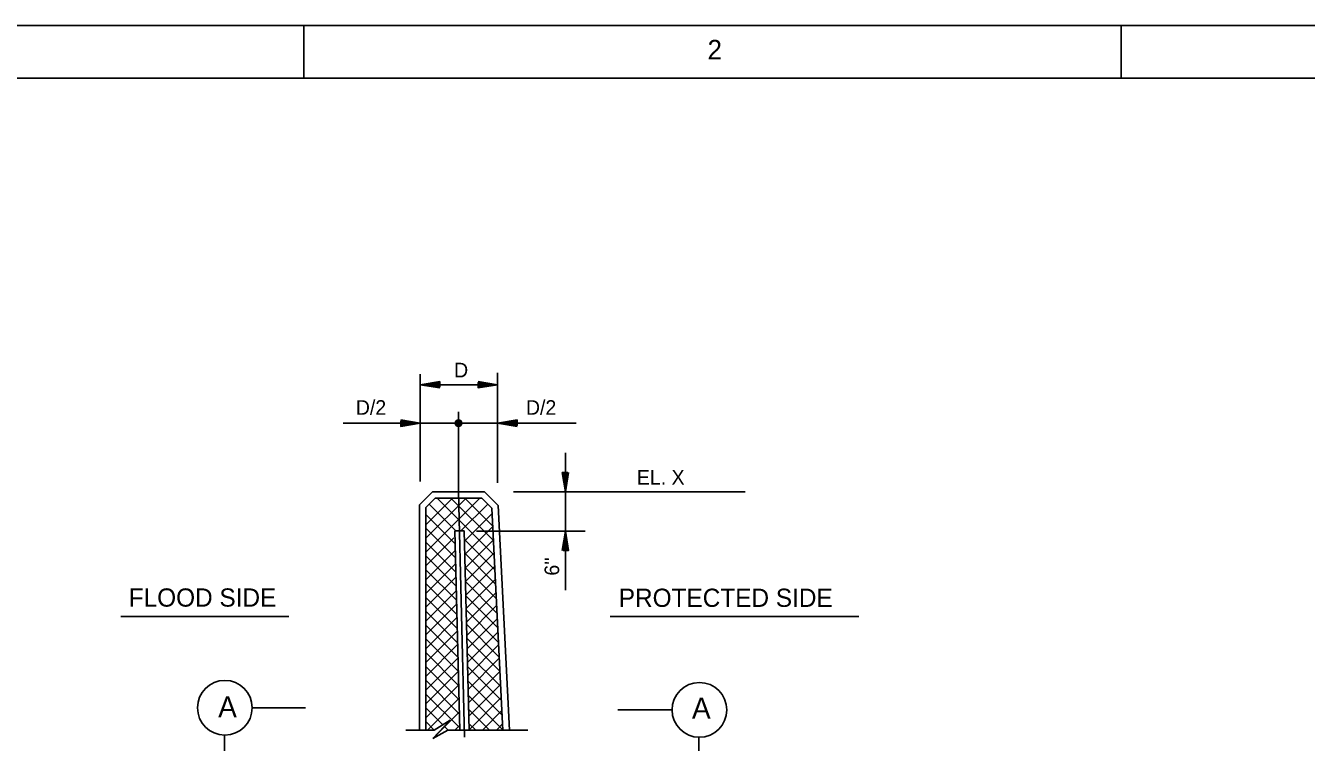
# Model space of a CAD drawing. Extents: x 44743.44 to 44747.1, y 44738.46 to 44741.29.
# Drawn here: x 44743.993 to 44745.018, y 44740.718 to 44741.292 of the extents above; entities that cross this region are included whole.
import ezdxf

# ---------------------------------------------------------------- set-up
doc = ezdxf.new("R2010")
doc.units = 0
for name, color, linetype in [('Level 1', 7, 'Continuous'), ('Level 10', 7, 'Continuous'), ('Level 2', 7, 'Continuous'), ('Level 3', 7, 'Continuous'), ('Level 8', 7, 'Continuous'), ('Level 9', 7, 'Continuous'), ('S-ANNO-TEXT', 7, 'Continuous')]:
    doc.layers.add(name, color=color, linetype=linetype)

msp = doc.modelspace()

# ---------------------------------------------------------------- linework, layer by layer
at = {"layer": 'Level 1'}
for p, q in [((44744.3088, 44740.927), (44744.3088, 44741.0131)), ((44744.3708, 44740.9261), (44744.3708, 44741.014)), ((44744.3088, 44741.0045), (44744.3708, 44741.0045)), ((44744.3088, 44741.0045), (44744.3088, 44741.0045)), ((44744.3131, 44741.0045), (44744.3131, 44741.0045)), ((44744.3664, 44741.0045), (44744.3664, 44741.0045)), ((44744.3708, 44741.0045), (44744.3708, 44741.0045)), ((44744.3394, 44740.9189), (44744.3394, 44740.9829)), ((44744.2472, 44740.9738), (44744.3088, 44740.9738)), ((44744.3044, 44740.9738), (44744.3044, 44740.9738)), ((44744.3088, 44740.9738), (44744.3708, 44740.9738)), ((44744.3088, 44740.9738), (44744.3088, 44740.9738)), ((44744.4336, 44740.9738), (44744.3708, 44740.9738)), ((44744.3708, 44740.9738), (44744.3708, 44740.9738)), ((44744.3751, 44740.9738), (44744.3751, 44740.9738)), ((44744.4251, 44740.9188), (44744.4251, 44740.95)), ((44744.3394, 44740.9189), (44744.3443, 44740.7225)), ((44744.3834, 44740.9188), (44744.5689, 44740.9188)), ((44744.4251, 44740.9231), (44744.4251, 44740.9231)), ((44744.4251, 44740.9188), (44744.4251, 44740.8875)), ((44744.4251, 44740.9188), (44744.4251, 44740.9188)), ((44744.3539, 44740.8875), (44744.4407, 44740.8875)), ((44744.4251, 44740.8402), (44744.4251, 44740.8875)), ((44744.4251, 44740.8875), (44744.4251, 44740.8875)), ((44744.4251, 44740.8832), (44744.4251, 44740.8832)), ((44744.32, 44740.7283), (44744.3133, 44740.735)), ((44744.3329, 44740.7361), (44744.319, 44740.7215)), ((44744.3199, 44740.7283), (44744.3329, 44740.7361)), ((44744.2974, 44740.7283), (44744.3199, 44740.7283)), ((44744.3091, 44740.7283), (44744.3082, 44740.7291)), ((44744.319, 44740.7215), (44744.3308, 44740.7283)), ((44744.3311, 44740.7283), (44744.3282, 44740.7312)), ((44744.3308, 44740.7283), (44744.395, 44740.7283))]:
    msp.add_line(p, q, dxfattribs=at)
msp.add_lwpolyline([(44743.438, 44741.2918), (44747.1047, 44741.2918), (44747.1047, 44738.4578), (44743.438, 44738.4578)], close=True, dxfattribs=at)
for points in [[(44744.3244, 44741.002), (44744.3088, 44741.0045), (44744.3244, 44741.0071), (44744.3244, 44741.0027), (44744.3131, 44741.0045), (44744.3237, 44741.0063), (44744.3237, 44741.0035), (44744.3173, 44741.0045), (44744.323, 44741.0055), (44744.323, 44741.0043), (44744.3216, 44741.0045)], [(44744.3552, 44741.0071), (44744.3708, 44741.0045), (44744.3552, 44741.002), (44744.3552, 44741.0064), (44744.3664, 44741.0045), (44744.3558, 44741.0028), (44744.3558, 44741.0056), (44744.3623, 44741.0045), (44744.3565, 44741.0036), (44744.3565, 44741.0048), (44744.3579, 44741.0045)], [(44744.2932, 44740.9764), (44744.3088, 44740.9738), (44744.2932, 44740.9712), (44744.2932, 44740.9756), (44744.3044, 44740.9738), (44744.2939, 44740.972), (44744.2939, 44740.9749), (44744.3003, 44740.9738), (44744.2945, 44740.9729), (44744.2945, 44740.974), (44744.2959, 44740.9738)], [(44744.3863, 44740.9712), (44744.3708, 44740.9738), (44744.3863, 44740.9764), (44744.3863, 44740.9719), (44744.3751, 44740.9738), (44744.3857, 44740.9755), (44744.3857, 44740.9727), (44744.3793, 44740.9738), (44744.385, 44740.9747), (44744.385, 44740.9735), (44744.3836, 44740.9738)], [(44744.4276, 44740.9343), (44744.4251, 44740.9188), (44744.4225, 44740.9343), (44744.4269, 44740.9343), (44744.4251, 44740.9231), (44744.4233, 44740.9337), (44744.4261, 44740.9337), (44744.4251, 44740.9273), (44744.4241, 44740.933), (44744.4253, 44740.933), (44744.4251, 44740.9316)], [(44744.4225, 44740.872), (44744.4251, 44740.8875), (44744.4276, 44740.872), (44744.4232, 44740.872), (44744.4251, 44740.8832), (44744.4268, 44740.8726), (44744.424, 44740.8726), (44744.4251, 44740.879), (44744.426, 44740.8733), (44744.4248, 44740.8733), (44744.4251, 44740.8747)]]:
    msp.add_lwpolyline(points, dxfattribs=at)
at = {"layer": 'Level 10'}
for p, q in [((44744.2157, 44741.2498), (44744.2157, 44741.2918)), ((44744.8697, 44741.2498), (44744.8697, 44741.2918)), ((44744.3186, 44740.9189), (44744.3082, 44740.9085)), ((44744.3186, 44740.9189), (44744.3602, 44740.9189)), ((44744.3602, 44740.9189), (44744.3712, 44740.908)), ((44744.3082, 44740.9085), (44744.3082, 44740.7283)), ((44744.3712, 44740.908), (44744.3802, 44740.7283)), ((44744.0693, 44740.8191), (44744.2036, 44740.8191)), ((44744.6597, 44740.8191), (44744.4608, 44740.8191))]:
    msp.add_line(p, q, dxfattribs=at)
at = {"layer": 'Level 2'}
for p, q in [((44744.3422, 44740.9738), (44744.337, 44740.9738)), ((44744.3418, 44740.9751), (44744.3373, 44740.9751)), ((44744.3418, 44740.9725), (44744.3373, 44740.9725)), ((44744.3389, 44740.9712), (44744.3397, 44740.9712)), ((44744.3207, 44740.9138), (44744.3133, 44740.9064)), ((44744.3207, 44740.9138), (44744.3581, 44740.9138)), ((44744.3581, 44740.9138), (44744.3661, 44740.9057)), ((44744.3133, 44740.9064), (44744.3133, 44740.7283)), ((44744.3661, 44740.9057), (44744.375, 44740.728)), ((44744.3365, 44740.8877), (44744.344, 44740.8877)), ((44744.3365, 44740.8877), (44744.3405, 44740.7283)), ((44744.344, 44740.8877), (44744.3479, 44740.7283))]:
    msp.add_line(p, q, dxfattribs=at)
msp.add_circle((44744.3395, 44740.9738), 0.00261, dxfattribs=at)
at = {"layer": 'Level 3'}
for p, q in [((44744.217, 44740.7461), (44744.1739, 44740.7461)), ((44744.4669, 44740.7444), (44744.5099, 44740.7444)), ((44744.1521, 44740.7097), (44744.1521, 44740.7243)), ((44744.5318, 44740.7079), (44744.5318, 44740.7225))]:
    msp.add_line(p, q, dxfattribs=at)
for centre in [(44744.1525, 44740.7461), (44744.5322, 44740.7444)]:
    msp.add_circle(centre, 0.0219, dxfattribs=at)
at = {"layer": 'Level 8'}
for p, q in [((44744.3133, 44740.8706), (44744.3565, 44740.9138)), ((44744.3133, 44740.8817), (44744.3455, 44740.9138)), ((44744.3133, 44740.8925), (44744.3346, 44740.9138)), ((44744.3161, 44740.9091), (44744.3374, 44740.8877)), ((44744.368, 44740.8682), (44744.3224, 44740.9138)), ((44744.3674, 44740.8798), (44744.3334, 44740.9138)), ((44744.3414, 44740.8877), (44744.3628, 44740.9091)), ((44744.3669, 44740.8914), (44744.3445, 44740.9138)), ((44744.3367, 44740.8773), (44744.3133, 44740.9007)), ((44744.3442, 44740.8794), (44744.3664, 44740.9016)), ((44744.337, 44740.866), (44744.3133, 44740.8897)), ((44744.3444, 44740.8686), (44744.3669, 44740.891)), ((44744.3133, 44740.8596), (44744.3358, 44740.882)), ((44744.3373, 44740.8547), (44744.3133, 44740.8786)), ((44744.3686, 44740.8565), (44744.3441, 44740.881)), ((44744.3447, 44740.8578), (44744.3674, 44740.8805)), ((44744.3133, 44740.8485), (44744.3368, 44740.872)), ((44744.3376, 44740.8434), (44744.3133, 44740.8676)), ((44744.3692, 44740.8449), (44744.3444, 44740.8697)), ((44744.345, 44740.847), (44744.3679, 44740.87)), ((44744.3133, 44740.8375), (44744.3371, 44740.8613)), ((44744.3698, 44740.8332), (44744.3447, 44740.8583)), ((44744.3452, 44740.8363), (44744.3685, 44740.8595)), ((44744.3378, 44740.8321), (44744.3133, 44740.8565)), ((44744.3133, 44740.8265), (44744.3374, 44740.8505)), ((44744.3704, 44740.8216), (44744.345, 44740.847)), ((44744.3455, 44740.8255), (44744.369, 44740.849)), ((44744.3381, 44740.8207), (44744.3133, 44740.8454)), ((44744.3133, 44740.8154), (44744.3377, 44740.8397)), ((44744.3458, 44740.8147), (44744.3695, 44740.8384)), ((44744.3384, 44740.8094), (44744.3133, 44740.8344)), ((44744.3133, 44740.8044), (44744.3379, 44740.8289)), ((44744.3709, 44740.81), (44744.3453, 44740.8357)), ((44744.3461, 44740.8039), (44744.37, 44740.8279)), ((44744.3387, 44740.798), (44744.3133, 44740.8233)), ((44744.3133, 44740.7933), (44744.3382, 44740.8182)), ((44744.3715, 44740.7984), (44744.3455, 44740.8244)), ((44744.3463, 44740.7932), (44744.3706, 44740.8174)), ((44744.339, 44740.7867), (44744.3133, 44740.8123)), ((44744.3133, 44740.7823), (44744.3385, 44740.8074)), ((44744.3721, 44740.7867), (44744.3458, 44740.813)), ((44744.3466, 44740.7824), (44744.3711, 44740.8069)), ((44744.3393, 44740.7753), (44744.3133, 44740.8012)), ((44744.3133, 44740.7712), (44744.3387, 44740.7966)), ((44744.3727, 44740.7751), (44744.3461, 44740.8017)), ((44744.3469, 44740.7716), (44744.3716, 44740.7964)), ((44744.3395, 44740.764), (44744.3133, 44740.7902)), ((44744.3133, 44740.7602), (44744.339, 44740.7858)), ((44744.3733, 44740.763), (44744.3467, 44740.7896)), ((44744.3471, 44740.7608), (44744.3721, 44740.7858)), ((44744.3398, 44740.7527), (44744.3133, 44740.7791)), ((44744.3738, 44740.7518), (44744.3467, 44740.779)), ((44744.3474, 44740.7501), (44744.3727, 44740.7753)), ((44744.3133, 44740.7492), (44744.3393, 44740.7751)), ((44744.3401, 44740.7413), (44744.3133, 44740.7681)), ((44744.3744, 44740.7402), (44744.347, 44740.7676)), ((44744.3133, 44740.7381), (44744.3395, 44740.7643)), ((44744.3404, 44740.73), (44744.3133, 44740.757)), ((44744.3753, 44740.7283), (44744.3472, 44740.7563)), ((44744.3477, 44740.7393), (44744.3732, 44740.7648)), ((44744.3269, 44740.7325), (44744.3133, 44740.746)), ((44744.3146, 44740.7283), (44744.3398, 44740.7535)), ((44744.3642, 44740.7283), (44744.3475, 44740.745)), ((44744.3479, 44740.7285), (44744.3737, 44740.7543)), ((44744.3215, 44740.7242), (44744.3401, 44740.7427)), ((44744.3587, 44740.7283), (44744.3742, 44740.7438)), ((44744.3366, 44740.7283), (44744.3403, 44740.732)), ((44744.3532, 44740.7283), (44744.3478, 44740.7336)), ((44744.3698, 44740.7283), (44744.3748, 44740.7333))]:
    msp.add_line(p, q, dxfattribs=at)
at = {"layer": 'Level 9'}
msp.add_line((44743.563, 44741.2498), (44746.8337, 44741.2498), dxfattribs=at)

# ---------------------------------------------------------------- texts
at = {"layer": 'Level 1'}
msp.add_text('2', height=0.0156, dxfattribs=at).set_placement((44744.5387, 44741.2648))
at = {"layer": 'Level 10'}
for s, height, p in [('FLOOD SIDE', 0.01458, (44744.0756, 44740.827)), ('PROTECTED SIDE', 0.014583, (44744.4677, 44740.8268))]:
    msp.add_text(s, height=height, dxfattribs=at).set_placement(p)
at = {"layer": 'Level 3'}
for p in [(44744.1472, 44740.7385), (44744.5263, 44740.7375)]:
    msp.add_text('A', height=0.0167, dxfattribs=at).set_placement(p)
at = {"layer": 'S-ANNO-TEXT'}
for s, height, p in [('D', 0.0117, (44744.3359, 44741.0104)), ('D/2', 0.01167, (44744.2573, 44740.9805)), ('D/2', 0.01167, (44744.3934, 44740.9805)), ('EL. X', 0.01167, (44744.4822, 44740.9246))]:
    msp.add_text(s, height=height, dxfattribs=at).set_placement(p)
msp.add_text("6''", height=0.01167, rotation=90, dxfattribs=at).set_placement((44744.42, 44740.8518))

doc.saveas('drawing.dxf')
